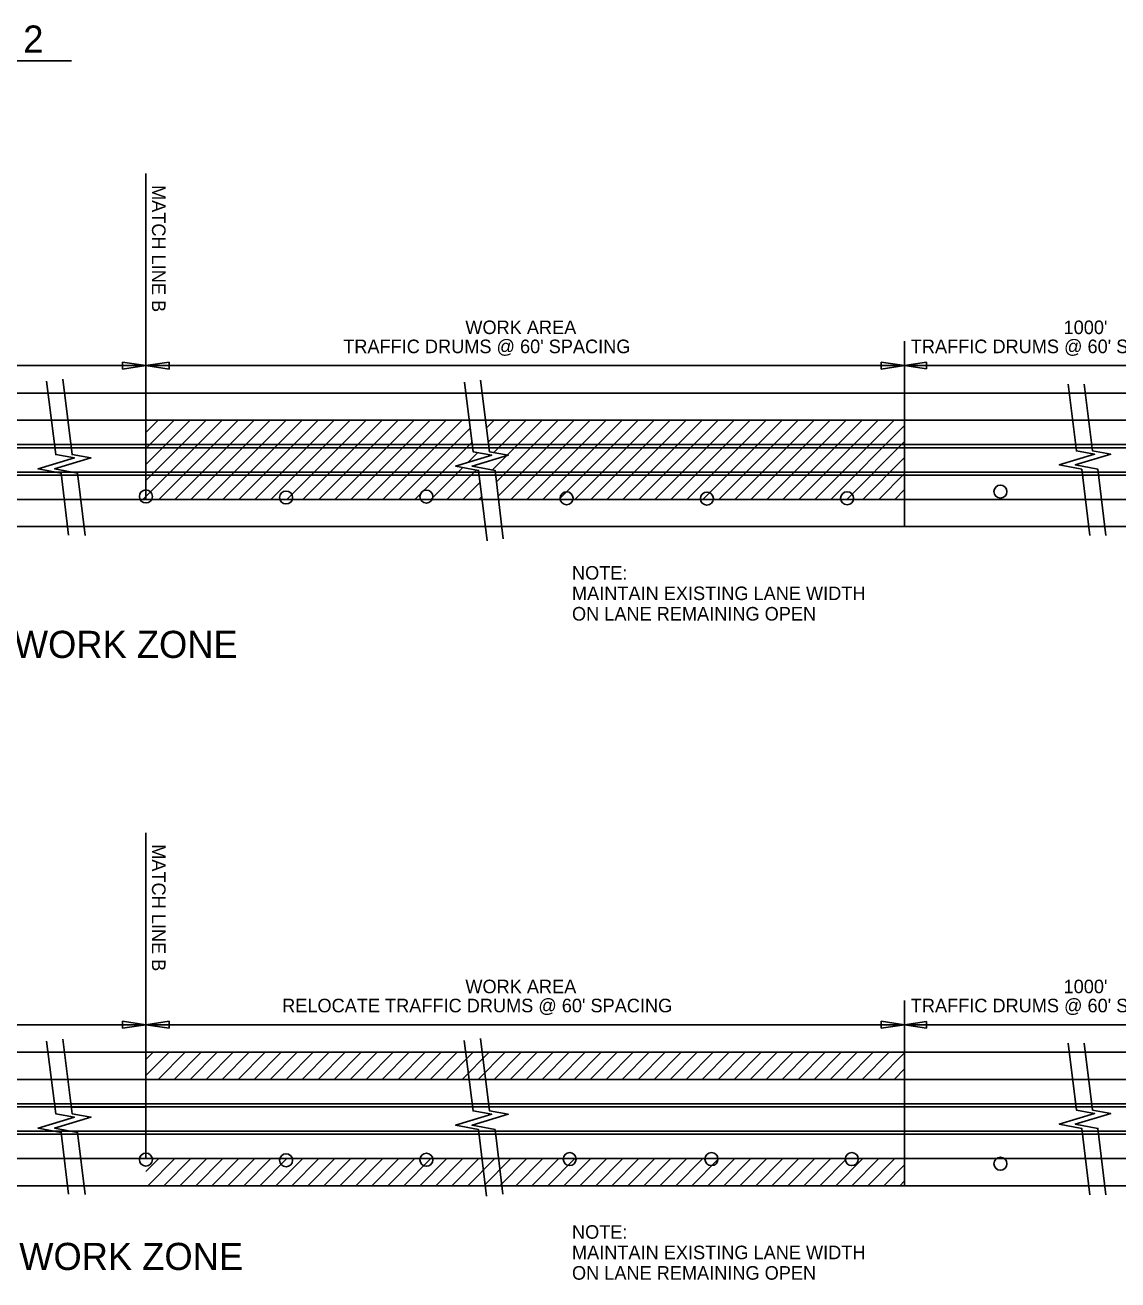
# Model space of a CAD drawing. Extents: x 1930579 to 1937984, y 596452 to 597630.
# Drawn here: x 1936944 to 1937427, y 596642 to 597197 of the extents above; entities that cross this region are included whole.
import ezdxf

# ---------------------------------------------------------------- set-up
doc = ezdxf.new("R2010")
doc.units = 0
doc.layers.add('Default', color=7, linetype='Continuous')
doc.layers.add('R_Annotation', color=7, linetype='Continuous')

msp = doc.modelspace()

# ---------------------------------------------------------------- linework, layer by layer
at = {"layer": 'Default'}
for p, q in [((1936835.84, 597181.22), (1936964.15, 597181.22)), ((1936997.05, 597131.34), (1936997.05, 596996.89)), ((1937332.4, 597057.24), (1937332.4, 596975.31)), ((1936997.05, 597046.45), (1936688.44, 597046.45)), ((1936986.74, 597044.9), (1936986.74, 597048)), ((1936986.74, 597048), (1936997.05, 597046.45)), ((1936997.05, 597046.45), (1936986.74, 597044.9)), ((1936997.05, 597046.45), (1937007.35, 597048)), ((1936997.05, 597047.93), (1936997.05, 596996.89)), ((1936997.05, 597047.92), (1936997.05, 596996.89)), ((1936997.05, 597047.92), (1936997.05, 596987.31)), ((1937332.4, 597046.45), (1936997.05, 597046.45)), ((1937007.35, 597044.9), (1936997.05, 597046.45)), ((1937007.35, 597048), (1937007.35, 597044.9)), ((1937322.09, 597044.9), (1937322.09, 597047.99)), ((1937322.09, 597047.99), (1937332.4, 597046.45)), ((1937332.4, 597046.45), (1937322.09, 597044.9)), ((1937332.4, 597046.45), (1937342.06, 597047.9)), ((1937342.06, 597045), (1937332.4, 597046.45)), ((1937498.74, 597046.45), (1937332.4, 597046.45)), ((1937342.06, 597047.9), (1937342.06, 597045)), ((1937498.74, 597034.31), (1936493.11, 597034.31)), ((1936493.11, 597022.31), (1937498.74, 597022.31)), ((1936995.74, 596987.31), (1937030.74, 597022.31)), ((1936997.05, 596995.68), (1937023.67, 597022.31)), ((1936997.05, 597002.75), (1937016.6, 597022.31)), ((1936997.05, 597009.83), (1937009.53, 597022.31)), ((1936997.05, 597016.9), (1937002.46, 597022.31)), ((1937002.81, 596987.31), (1937037.81, 597022.31)), ((1937009.89, 596987.31), (1937044.89, 597022.31)), ((1937016.96, 596987.31), (1937051.96, 597022.31)), ((1937024.03, 596987.31), (1937059.03, 597022.31)), ((1937031.1, 596987.31), (1937066.1, 597022.31)), ((1937038.17, 596987.31), (1937073.17, 597022.31)), ((1937045.24, 596987.31), (1937080.24, 597022.31)), ((1937052.31, 596987.31), (1937087.31, 597022.31)), ((1937059.38, 596987.31), (1937094.38, 597022.31)), ((1937066.45, 596987.31), (1937101.45, 597022.31)), ((1937073.53, 596987.31), (1937108.53, 597022.31)), ((1937080.6, 596987.31), (1937115.6, 597022.31)), ((1937087.67, 596987.31), (1937122.67, 597022.31)), ((1937094.74, 596987.31), (1937129.74, 597022.31)), ((1937101.81, 596987.31), (1937136.81, 597022.31)), ((1937147.64, 597018.99), (1937150.95, 597022.31)), ((1937148.42, 597012.71), (1937158.02, 597022.31)), ((1937150.83, 597008.04), (1937165.09, 597022.31)), ((1937152, 596995.07), (1937179.24, 597022.31)), ((1937152.76, 596988.76), (1937186.31, 597022.31)), ((1937156.84, 597006.98), (1937172.17, 597022.31)), ((1937158.38, 596987.31), (1937193.38, 597022.31)), ((1937165.45, 596987.31), (1937200.45, 597022.31)), ((1937172.52, 596987.31), (1937207.52, 597022.31)), ((1937179.59, 596987.31), (1937214.59, 597022.31)), ((1937186.66, 596987.31), (1937221.66, 597022.31)), ((1937193.73, 596987.31), (1937228.73, 597022.31)), ((1937200.8, 596987.31), (1937235.8, 597022.31)), ((1937207.88, 596987.31), (1937242.88, 597022.31)), ((1937214.95, 596987.31), (1937249.95, 597022.31)), ((1937222.02, 596987.31), (1937257.02, 597022.31)), ((1937229.09, 596987.31), (1937264.09, 597022.31)), ((1937236.16, 596987.31), (1937271.16, 597022.31)), ((1937243.23, 596987.31), (1937278.23, 597022.31)), ((1937250.3, 596987.31), (1937285.3, 597022.31)), ((1937257.37, 596987.31), (1937292.37, 597022.31)), ((1937264.44, 596987.31), (1937299.44, 597022.31)), ((1937271.52, 596987.31), (1937306.52, 597022.31)), ((1937278.59, 596987.31), (1937313.59, 597022.31)), ((1937285.66, 596987.31), (1937320.66, 597022.31)), ((1937292.73, 596987.31), (1937327.73, 597022.31)), ((1937108.88, 596987.31), (1937140.38, 597018.81)), ((1937299.8, 596987.31), (1937332.4, 597019.91)), ((1937498.74, 597011.52), (1936493.11, 597011.52)), ((1937498.74, 597010.14), (1936493.11, 597010.14)), ((1937115.95, 596987.31), (1937141.16, 597012.52)), ((1937306.87, 596987.31), (1937332.4, 597012.83)), ((1937139.45, 597003.73), (1937143.72, 597008.01)), ((1937150.22, 597000.37), (1937156.57, 597006.72)), ((1937313.94, 596987.31), (1937332.4, 597005.76)), ((1937498.74, 596999.41), (1936493.11, 596999.41)), ((1937123.02, 596987.31), (1937137.15, 597001.44)), ((1937130.09, 596987.31), (1937143.09, 597000.3)), ((1937321.01, 596987.31), (1937332.4, 596998.69)), ((1937498.74, 596998.03), (1936493.11, 596998.03)), ((1937137.17, 596987.31), (1937144.74, 596994.88)), ((1936493.11, 596987.31), (1937498.74, 596987.31)), ((1937144.24, 596987.31), (1937145.5, 596988.57)), ((1937328.08, 596987.31), (1937332.4, 596991.62)), ((1937498.74, 596975.31), (1936493.11, 596975.31)), ((1936757.75, 596975.31), (1937032.82, 596975.31)), ((1936970.07, 596975.31), (1936996.83, 596975.31)), ((1936996.83, 596975.31), (1937147.44, 596975.31)), ((1937155.09, 596975.31), (1937332.4, 596975.31)), ((1936997.05, 596839.97), (1936997.05, 596705.52)), ((1937332.4, 596765.87), (1937332.4, 596683.94)), ((1936997.05, 596755.08), (1936688.44, 596755.08)), ((1936986.74, 596753.53), (1936986.74, 596756.63)), ((1936986.74, 596756.63), (1936997.05, 596755.08)), ((1936997.05, 596755.08), (1936986.74, 596753.53)), ((1936997.05, 596755.08), (1937007.35, 596756.63)), ((1936997.05, 596756.56), (1936997.05, 596705.52)), ((1936997.05, 596756.55), (1936997.05, 596705.52)), ((1936997.05, 596756.55), (1936997.05, 596695.94)), ((1937332.4, 596755.08), (1936997.05, 596755.08)), ((1937007.35, 596753.53), (1936997.05, 596755.08)), ((1937007.35, 596756.63), (1937007.35, 596753.53)), ((1937322.09, 596753.53), (1937322.09, 596756.62)), ((1937322.09, 596756.62), (1937332.4, 596755.08)), ((1937332.4, 596755.08), (1937322.09, 596753.53)), ((1937332.4, 596755.08), (1937342.06, 596756.53)), ((1937498.74, 596755.08), (1937332.4, 596755.08)), ((1937342.06, 596753.63), (1937332.4, 596755.08)), ((1937342.06, 596756.53), (1937342.06, 596753.63)), ((1937498.74, 596742.94), (1936493.11, 596742.94)), ((1936997.05, 596732.6), (1937007.39, 596742.94)), ((1936997.05, 596739.67), (1937000.32, 596742.94)), ((1937002.46, 596730.94), (1937014.46, 596742.94)), ((1937009.53, 596730.94), (1937021.53, 596742.94)), ((1937016.6, 596730.94), (1937028.6, 596742.94)), ((1937023.67, 596730.94), (1937035.67, 596742.94)), ((1937030.74, 596730.94), (1937042.74, 596742.94)), ((1937037.81, 596730.94), (1937049.81, 596742.94)), ((1937044.89, 596730.94), (1937056.89, 596742.94)), ((1937051.96, 596730.94), (1937063.96, 596742.94)), ((1937059.03, 596730.94), (1937071.03, 596742.94)), ((1937066.1, 596730.94), (1937078.1, 596742.94)), ((1937073.17, 596730.94), (1937085.17, 596742.94)), ((1937080.24, 596730.94), (1937092.24, 596742.94)), ((1937087.31, 596730.94), (1937099.31, 596742.94)), ((1937094.38, 596730.94), (1937106.38, 596742.94)), ((1937101.45, 596730.94), (1937113.45, 596742.94)), ((1937108.53, 596730.94), (1937120.53, 596742.94)), ((1937115.6, 596730.94), (1937127.6, 596742.94)), ((1937122.67, 596730.94), (1937134.67, 596742.94)), ((1937129.74, 596730.94), (1937141.74, 596742.94)), ((1937136.81, 596730.94), (1937148.81, 596742.94)), ((1937143.88, 596730.94), (1937155.88, 596742.94)), ((1937150.95, 596730.94), (1937162.95, 596742.94)), ((1937158.02, 596730.94), (1937170.02, 596742.94)), ((1937165.09, 596730.94), (1937177.09, 596742.94)), ((1937172.17, 596730.94), (1937184.17, 596742.94)), ((1937179.24, 596730.94), (1937191.24, 596742.94)), ((1937186.31, 596730.94), (1937198.31, 596742.94)), ((1937193.38, 596730.94), (1937205.38, 596742.94)), ((1937200.45, 596730.94), (1937212.45, 596742.94)), ((1937207.52, 596730.94), (1937219.52, 596742.94)), ((1937214.59, 596730.94), (1937226.59, 596742.94)), ((1937221.66, 596730.94), (1937233.66, 596742.94)), ((1937228.73, 596730.94), (1937240.73, 596742.94)), ((1937235.8, 596730.94), (1937247.8, 596742.94)), ((1937242.88, 596730.94), (1937254.88, 596742.94)), ((1937249.95, 596730.94), (1937261.95, 596742.94)), ((1937257.02, 596730.94), (1937269.02, 596742.94)), ((1937264.09, 596730.94), (1937276.09, 596742.94)), ((1937271.16, 596730.94), (1937283.16, 596742.94)), ((1937278.23, 596730.94), (1937290.23, 596742.94)), ((1937285.3, 596730.94), (1937297.3, 596742.94)), ((1937292.37, 596730.94), (1937304.37, 596742.94)), ((1937299.44, 596730.94), (1937311.44, 596742.94)), ((1937306.52, 596730.94), (1937318.52, 596742.94)), ((1937313.59, 596730.94), (1937325.59, 596742.94)), ((1937320.66, 596730.94), (1937332.66, 596742.94)), ((1937327.73, 596730.94), (1937332.4, 596735.61)), ((1936493.11, 596730.94), (1937498.74, 596730.94)), ((1937498.74, 596720.15), (1936493.11, 596720.15)), ((1937498.74, 596718.77), (1936493.11, 596718.77)), ((1936964.36, 596718.71), (1936997.05, 596718.71)), ((1937498.74, 596708.04), (1936493.11, 596708.04)), ((1937498.74, 596706.66), (1936493.11, 596706.66)), ((1936493.11, 596695.94), (1937498.74, 596695.94)), ((1936997.05, 596690.17), (1937002.81, 596695.94)), ((1936997.89, 596683.94), (1937009.89, 596695.94)), ((1937004.96, 596683.94), (1937016.96, 596695.94)), ((1937012.03, 596683.94), (1937024.03, 596695.94)), ((1937019.1, 596683.94), (1937031.1, 596695.94)), ((1937026.17, 596683.94), (1937038.17, 596695.94)), ((1937033.24, 596683.94), (1937045.24, 596695.94)), ((1937040.31, 596683.94), (1937052.31, 596695.94)), ((1937047.38, 596683.94), (1937059.38, 596695.94)), ((1937054.45, 596683.94), (1937066.45, 596695.94)), ((1937061.53, 596683.94), (1937073.53, 596695.94)), ((1937068.6, 596683.94), (1937080.6, 596695.94)), ((1937075.67, 596683.94), (1937087.67, 596695.94)), ((1937082.74, 596683.94), (1937094.74, 596695.94)), ((1937089.81, 596683.94), (1937101.81, 596695.94)), ((1937096.88, 596683.94), (1937108.88, 596695.94)), ((1937103.95, 596683.94), (1937115.95, 596695.94)), ((1937111.02, 596683.94), (1937123.02, 596695.94)), ((1937118.09, 596683.94), (1937130.09, 596695.94)), ((1937125.17, 596683.94), (1937137.17, 596695.94)), ((1937132.24, 596683.94), (1937144.24, 596695.94)), ((1937139.31, 596683.94), (1937151.31, 596695.94)), ((1937146.38, 596683.94), (1937158.38, 596695.94)), ((1937153.45, 596683.94), (1937165.45, 596695.94)), ((1937160.52, 596683.94), (1937172.52, 596695.94)), ((1937167.59, 596683.94), (1937179.59, 596695.94)), ((1937174.66, 596683.94), (1937186.66, 596695.94)), ((1937181.73, 596683.94), (1937193.73, 596695.94)), ((1937188.8, 596683.94), (1937200.8, 596695.94)), ((1937195.88, 596683.94), (1937207.88, 596695.94)), ((1937202.95, 596683.94), (1937214.95, 596695.94)), ((1937210.02, 596683.94), (1937222.02, 596695.94)), ((1937217.09, 596683.94), (1937229.09, 596695.94)), ((1937224.16, 596683.94), (1937236.16, 596695.94)), ((1937231.23, 596683.94), (1937243.23, 596695.94)), ((1937238.3, 596683.94), (1937250.3, 596695.94)), ((1937245.37, 596683.94), (1937257.37, 596695.94)), ((1937252.44, 596683.94), (1937264.44, 596695.94)), ((1937259.52, 596683.94), (1937271.52, 596695.94)), ((1937266.59, 596683.94), (1937278.59, 596695.94)), ((1937273.66, 596683.94), (1937285.66, 596695.94)), ((1937280.73, 596683.94), (1937292.73, 596695.94)), ((1937287.8, 596683.94), (1937299.8, 596695.94)), ((1937294.87, 596683.94), (1937306.87, 596695.94)), ((1937301.94, 596683.94), (1937313.94, 596695.94)), ((1937309.01, 596683.94), (1937321.01, 596695.94)), ((1937316.08, 596683.94), (1937328.08, 596695.94)), ((1937323.16, 596683.94), (1937332.4, 596693.18)), ((1937498.74, 596683.94), (1936493.11, 596683.94)), ((1936757.75, 596683.94), (1937032.82, 596683.94)), ((1936970.07, 596683.94), (1936996.83, 596683.94)), ((1936996.83, 596683.94), (1937147.44, 596683.94)), ((1937155.09, 596683.94), (1937332.4, 596683.94)), ((1937330.23, 596683.94), (1937332.4, 596686.11))]:
    msp.add_line(p, q, dxfattribs=at)
for points in [[(1936953.13, 597039.54), (1936957.19, 597007.1), (1936965.44, 597005.64), (1936949.42, 597000.78), (1936959.62, 596998.84), (1936962.9, 596971.51)], [(1936960.31, 597040.43), (1936964.47, 597007.1), (1936972.73, 597005.64), (1936956.7, 597000.78), (1936966.9, 596998.84), (1936970.2, 596971.4)], [(1937137.85, 597039.06), (1937141.68, 597008.37), (1937149.94, 597006.91), (1937133.91, 597002.05), (1937144.11, 597000.11), (1937147.85, 596969.01)], [(1937145.02, 597039.96), (1937148.97, 597008.37), (1937157.22, 597006.91), (1937141.2, 597002.05), (1937151.39, 597000.11), (1937155.03, 596969.87)], [(1937404.64, 597038.31), (1937408.33, 597008.71), (1937416.4, 597007.29), (1937400.75, 597002.54), (1937410.71, 597000.64), (1937414.23, 596971.31)], [(1937411.75, 597038.31), (1937415.45, 597008.71), (1937423.51, 597007.29), (1937407.86, 597002.54), (1937417.82, 597000.64), (1937421.35, 596971.31)], [(1937144.97, 596749), (1937148.97, 596717), (1937157.22, 596715.54), (1937141.2, 596710.68), (1937151.39, 596708.74), (1937154.82, 596680.23)], [(1936953.18, 596747.77), (1936957.19, 596715.73), (1936965.44, 596714.27), (1936949.42, 596709.41), (1936959.62, 596707.47), (1936962.9, 596680.14)], [(1936960.36, 596748.67), (1936964.47, 596715.73), (1936972.73, 596714.27), (1936956.7, 596709.41), (1936966.9, 596707.47), (1936970.2, 596680.03)], [(1937137.8, 596748.1), (1937141.68, 596717), (1937149.94, 596715.54), (1937133.91, 596710.68), (1937144.11, 596708.74), (1937147.64, 596679.37)], [(1937404.64, 596746.94), (1937408.33, 596717.34), (1937416.4, 596715.92), (1937400.75, 596711.17), (1937410.71, 596709.27), (1937414.23, 596679.94)], [(1937411.75, 596746.94), (1937415.45, 596717.34), (1937423.51, 596715.92), (1937407.86, 596711.17), (1937417.82, 596709.27), (1937421.35, 596679.94)]]:
    msp.add_lwpolyline(points, dxfattribs=at)
for centre in [(1937374.75, 596990.76), (1936997.05, 596988.6), (1937059.04, 596988.15), (1937121.03, 596988.57), (1937183.02, 596987.81), (1937245.02, 596987.66), (1937307.01, 596987.81), (1936997.05, 596695.46), (1937059.04, 596695.18), (1937121.03, 596695.41), (1937184.37, 596695.7), (1937247.04, 596695.68), (1937309.04, 596695.68), (1937374.75, 596693.65)]:
    msp.add_circle(centre, 2.87, dxfattribs=at)

# ---------------------------------------------------------------- texts
for s, height, rotation, p in [('STAGES 1   & 2', 12, 360, (1936835.84, 597184.79)), ('MATCH LINE B', 6, 270, (1936999.75, 597126.26)), ('WORK AREA', 6, 360, (1937138.26, 597060.38)), ("1000'", 6, 360, (1937402.67, 597060.38)), ("TRAFFIC DRUMS @ 60' SPACING", 6, 360, (1937084.29, 597051.95)), ("TRAFFIC DRUMS @ 60' SPACING", 6, 360, (1937335.13, 597051.95)), ('DIVERSION FOR LT. LANE WORK ZONE', 12, 360, (1936733.6, 596917.22)), ('MATCH LINE B', 6, 270, (1936999.75, 596834.89)), ('WORK AREA', 6, 360, (1937138.26, 596769.01)), ("1000'", 6, 360, (1937402.67, 596769.01)), ("RELOCATE TRAFFIC DRUMS @ 60' SPACING", 6, 360, (1937057.29, 596760.58)), ("TRAFFIC DRUMS @ 60' SPACING", 6, 360, (1937335.13, 596760.58)), ('DIVERSION FOR RT. LANE WORK ZONE', 12, 360, (1936733.32, 596646.67))]:
    msp.add_text(s, height=height, rotation=rotation, dxfattribs=at).set_placement(p)
at = {"layer": 'R_Annotation'}
for s, p in [('NOTE:', (1937185.39, 596951.85)), ('MAINTAIN EXISTING LANE WIDTH', (1937185.39, 596942.8)), ('ON LANE REMAINING OPEN', (1937185.39, 596933.75)), ('NOTE:', (1937185.39, 596660.48)), ('MAINTAIN EXISTING LANE WIDTH', (1937185.39, 596651.43)), ('ON LANE REMAINING OPEN', (1937185.39, 596642.38))]:
    msp.add_text(s, height=6, rotation=360, dxfattribs=at).set_placement(p)

doc.saveas('drawing.dxf')
